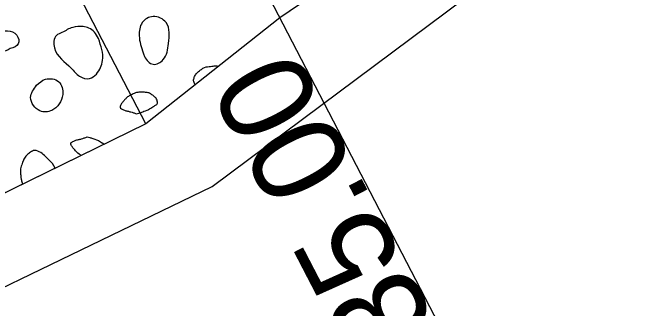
# Model space of a CAD drawing. Extents: x 2030588 to 2035216, y 462285 to 465007.
# Drawn here: x 2031353.85 to 2031372.89, y 464343.19 to 464352 of the extents above; entities that cross this region are included whole.
import ezdxf

# ---------------------------------------------------------------- set-up
doc = ezdxf.new("R2010")
doc.units = 0
for name, color, linetype in [('DR_P_Erosion_Control', 7, 'Continuous'), ('DT_P_Slope_Break_Line', 7, 'Continuous'), ('GE_P_Alignment_100_Cardinal_Points', 7, 'Continuous'), ('MD_P_CONST_LIMITS', 7, 'Continuous')]:
    doc.layers.add(name, color=color, linetype=linetype)

msp = doc.modelspace()

# ---------------------------------------------------------------- linework, layer by layer
at = {"layer": 'DR_P_Erosion_Control'}
msp.add_lwpolyline([(2031376.418, 464378.139), (2031377.38, 464376.641), (2031374.249, 464363.017), (2031371.043, 464358.759), (2031367.189, 464355.509), (2031361.811, 464351.851), (2031357.821, 464348.687), (2031353.329, 464346.49), (2031348.942, 464344.089), (2031341.686, 464358.066), (2031346.124, 464360.37), (2031350.791, 464362.229), (2031355.228, 464364.533), (2031359.594, 464367.328), (2031363.8, 464370.031), (2031368.006, 464372.733), (2031372.212, 464375.436)], close=True, dxfattribs=at)
for points in [[(2031357.735, 464350.807), (2031357.62, 464351.314), (2031357.713, 464351.705), (2031358.034, 464351.889), (2031358.424, 464351.705), (2031358.494, 464351.084), (2031358.333, 464350.601), (2031358.034, 464350.462), (2031357.782, 464350.692), (2031357.735, 464350.807)], [(2031353.774, 464350.929), (2031354.013, 464351.073), (2031353.971, 464351.335), (2031353.69, 464351.459), (2031353.275, 464351.376), (2031353.035, 464351.168), (2031352.993, 464350.97), (2031353.275, 464350.877), (2031353.514, 464350.834), (2031353.774, 464350.929)], [(2031356.406, 464351.229), (2031356.529, 464350.579), (2031356.343, 464350.172), (2031356.143, 464350.037), (2031355.845, 464350.106), (2031355.593, 464350.349), (2031355.091, 464350.949), (2031355.152, 464351.323), (2031355.318, 464351.415), (2031355.637, 464351.564), (2031355.948, 464351.585), (2031356.121, 464351.541), (2031356.286, 464351.424), (2031356.406, 464351.229)], [(2031354.559, 464349.84), (2031354.383, 464349.471), (2031354.661, 464349.073), (2031355.014, 464349.089), (2031355.339, 464349.56), (2031355.22, 464349.942), (2031354.824, 464350.016), (2031354.559, 464349.84)]]:
    msp.add_spline(points, degree=3, dxfattribs=at)
for points, degree in [([(2031359.291, 464349.852), (2031359.256, 464349.911), (2031359.237, 464349.971), (2031359.25, 464350.024), (2031359.276, 464350.127), (2031359.362, 464350.23), (2031359.479, 464350.316), (2031359.568, 464350.381), (2031359.658, 464350.388), (2031359.749, 464350.399), (2031359.815, 464350.407), (2031359.92, 464350.423), (2031359.995, 464350.41)], 3), ([(2031357.87, 464349.098), (2031357.95, 464349.146), (2031358.03, 464349.194), (2031358.11, 464349.243), (2031358.184, 464349.288), (2031358.145, 464349.438), (2031358.069, 464349.502), (2031357.98, 464349.578), (2031357.886, 464349.621), (2031357.787, 464349.628), (2031357.65, 464349.638), (2031357.506, 464349.615), (2031357.371, 464349.545), (2031357.27, 464349.493), (2031357.202, 464349.42), (2031357.132, 464349.337), (2031357.087, 464349.284), (2031357.032, 464349.174), (2031357.091, 464349.139), (2031357.177, 464349.086), (2031357.274, 464349.067), (2031357.371, 464349.044), (2031357.451, 464349.025), (2031357.535, 464348.976), (2031357.61, 464349.003), (2031357.694, 464349.034), (2031357.777, 464349.067), (2031357.861, 464349.098)], 3), ([(2031355.896, 464347.745), (2031355.799, 464347.798), (2031355.732, 464347.868), (2031355.663, 464347.95), (2031355.619, 464348.002), (2031355.564, 464348.111), (2031355.623, 464348.146), (2031355.709, 464348.199), (2031355.806, 464348.218), (2031355.903, 464348.241), (2031355.983, 464348.26), (2031356.066, 464348.309), (2031356.142, 464348.282), (2031356.229, 464348.251), (2031356.315, 464348.22), (2031356.402, 464348.189)], 3), ([(2031356.402, 464348.189), (2031356.461, 464348.153), (2031356.521, 464348.116), (2031356.58, 464348.08)], 2), ([(2031355.11, 464347.361), (2031355.065, 464347.477), (2031354.933, 464347.604), (2031354.828, 464347.707), (2031354.695, 464347.837), (2031354.496, 464347.921), (2031354.372, 464347.838), (2031354.275, 464347.773), (2031354.194, 464347.667), (2031354.146, 464347.545), (2031354.084, 464347.389), (2031354.075, 464347.227), (2031354.097, 464347.073), (2031354.106, 464347.009), (2031354.118, 464346.948), (2031354.14, 464346.887)], 3)]:
    msp.add_open_spline(points, degree=degree, dxfattribs=at)
at = {"layer": 'DT_P_Slope_Break_Line'}
for p, q in [((2031357.821, 464348.687), (2031350.791, 464362.229)), ((2031367.189, 464355.509), (2031361.811, 464351.851)), ((2031361.811, 464351.851), (2031357.821, 464348.687)), ((2031357.821, 464348.687), (2031353.329, 464346.49))]:
    msp.add_line(p, q, dxfattribs=at)
at = {"layer": 'GE_P_Alignment_100_Cardinal_Points'}
msp.add_line((2031354.307, 464366.308), (2031375.038, 464326.372), dxfattribs=at)
at = {"layer": 'MD_P_CONST_LIMITS'}
msp.add_lwpolyline([(2031335.72, 464342.732), (2031348.065, 464341.156), (2031359.796, 464346.821), (2031370.029, 464354.448), (2031376.828, 464361.456), (2031382.871, 464378.84), (2031377.102, 464386.742), (2031358.079, 464381.314), (2031336.103, 464372.313), (2031297.636, 464355.997), (2031288.946, 464369.084), (2031270.232, 464370.675), (2031259.85, 464435.069), (2031243.038, 464457.678), (2031227.121, 464556.394)], dxfattribs=at)

# ---------------------------------------------------------------- texts
at = {"layer": 'GE_P_Alignment_100_Cardinal_Points'}
msp.add_text('0+35.00', height=2.7997, rotation=117.4336, dxfattribs=at).set_placement((2031368.466, 464338.94))

doc.saveas('drawing.dxf')
